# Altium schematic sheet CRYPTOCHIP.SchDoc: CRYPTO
size A4; Author: Silvio Navaretti; CompanyName: Arduino srl; DocumentNumber: ABX00063; Revision: V1.2; SheetNumber: 8; SheetTotal: 8; RevAuthor: Silvio Navaretti
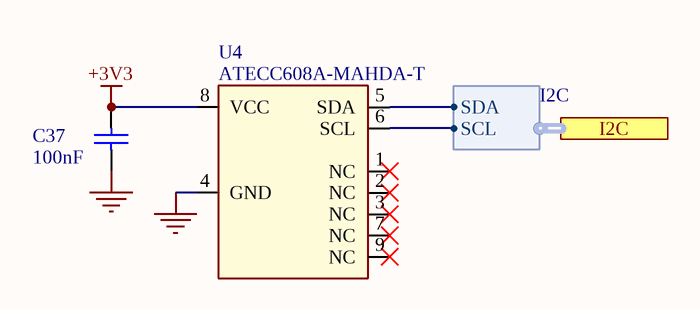
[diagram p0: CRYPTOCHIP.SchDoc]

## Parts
C37  value 100nF  [CAP-0402]  (hidden comment: GRM155R61H104KE19D)
U4  ATECC608A-MAHDA-T  [UDFN8]

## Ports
I2C (harness I2C)

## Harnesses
I2C: SDA, SCL

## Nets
+3V3: C37.2 U4.8(VCC)
GND: C37.1 U4.4(GND)
NetU4_5: U4.5(SDA) ; port I2C.SDA
NetU4_6: U4.6(SCL) ; port I2C.SCL

Not connected (* = marked no-connect by the designer): U4 1(NC)* 2(NC)* 3(NC)* 7(NC)* 9(NC)*

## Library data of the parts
C37 = C0015-A.11: CAP CHIP 0402 100nF 50V X5R 10%; Manufacturer: Murata; Code Arduino: A5141
U4 = U0034-A.5: IC AUTHENTICATION CHIP UDFN8; Manufacturer: Microchip; Code Arduino: U0034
